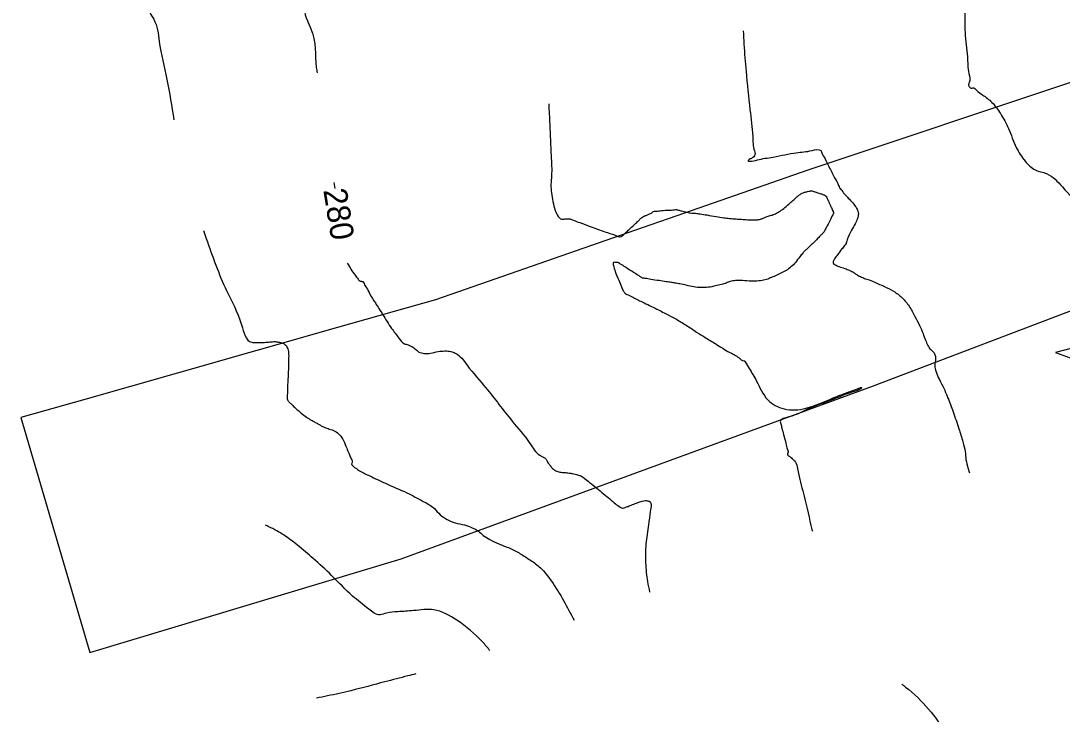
# Model space of a CAD drawing. Extents: x -478464 to -472469, y -1120963 to -1113785.
# Drawn here: x -476249.6 to -476071.3, y -1115360.9 to -1115242.1 of the extents above; entities that cross this region are included whole.
import ezdxf

# ---------------------------------------------------------------- set-up
doc = ezdxf.new("R2010")
doc.units = 0
for name, color, linetype in [('ObPÚ', 7, 'Continuous'), ('Vrstevnice_hlavni', 7, 'Continuous'), ('Vrstevnice_popis', 7, 'Continuous'), ('Vrstevnice_vedlejsi', 7, 'Continuous')]:
    doc.layers.add(name, color=color, linetype=linetype)

msp = doc.modelspace()

# ---------------------------------------------------------------- linework, layer by layer
at = {"layer": 'ObPÚ'}
for points in [[(-476068.7, -1115252.31), (-476114.88, -1115267.73), (-476138.618, -1115276.003), (-476141.91, -1115277.15), (-476168.45, -1115286.39), (-476178.6, -1115289.93), (-476195.38, -1115294.7), (-476223.04, -1115302.55), (-476238.65, -1115306.98), (-476249.64, -1115310.1), (-476237.84, -1115350.34), (-476184.5, -1115334.29), (-476103.79, -1115304.74), (-476065.34, -1115290.09)], [(-476062.5, -1115296.39), (-476072.47, -1115298.98), (-476067.44, -1115300.76)]]:
    msp.add_lwpolyline(points, dxfattribs=at)
at = {"layer": 'Vrstevnice_hlavni'}
msp.add_line((-476196.015, -1115269.846), (-476195.861, -1115270.85), dxfattribs=at)
for points in [[(-476040.384, -1115118.458), (-476041.47, -1115119.89), (-476042.412, -1115121.448), (-476043.751, -1115123.849), (-476045.488, -1115127.091), (-476046.696, -1115129.513), (-476047.375, -1115131.113), (-476047.526, -1115131.894), (-476048.073, -1115133.254), (-476049.018, -1115135.194), (-476050.36, -1115137.713), (-476052.374, -1115140.598), (-476055.061, -1115143.847), (-476058.422, -1115147.462), (-476060.881, -1115150.366), (-476062.441, -1115152.562), (-476063.1, -1115154.048), (-476064.028, -1115155.224), (-476065.225, -1115156.09), (-476066.691, -1115156.645), (-476068.203, -1115157.501), (-476069.761, -1115158.657), (-476071.364, -1115160.113), (-476073.585, -1115161.644), (-476076.424, -1115163.251), (-476079.881, -1115164.932), (-476082.243, -1115166.084), (-476083.511, -1115166.709), (-476083.684, -1115166.806), (-476083.884, -1115166.906), (-476084.109, -1115167.009), (-476084.361, -1115167.115), (-476085.47, -1115168.111), (-476087.436, -1115169.998), (-476090.259, -1115172.776), (-476094.056, -1115175.649), (-476098.828, -1115178.618), (-476104.575, -1115181.683), (-476109.757, -1115183.949), (-476114.374, -1115185.417), (-476118.425, -1115186.088), (-476122.042, -1115187.328), (-476125.226, -1115189.137), (-476127.977, -1115191.516), (-476131.019, -1115193.792), (-476134.353, -1115195.963), (-476137.979, -1115198.031), (-476141.984, -1115199.581), (-476146.368, -1115200.612), (-476151.132, -1115201.124), (-476157.864, -1115204.368), (-476166.565, -1115210.343), (-476177.234, -1115219.049), (-476184.652, -1115224.996), (-476188.817, -1115228.184), (-476189.731, -1115228.613), (-476190.168, -1115228.886), (-476190.128, -1115229.002), (-476189.61, -1115228.963), (-476189.269, -1115228.999), (-476189.104, -1115229.11), (-476189.116, -1115229.298), (-476189.143, -1115229.675), (-476189.187, -1115230.241), (-476189.246, -1115230.996), (-476189.162, -1115231.612), (-476188.933, -1115232.089), (-476188.56, -1115232.427), (-476188.448, -1115232.74), (-476188.595, -1115233.026), (-476189.004, -1115233.287), (-476189.464, -1115233.625), (-476189.976, -1115234.04), (-476190.541, -1115234.531), (-476191.953, -1115235.382), (-476194.211, -1115236.59), (-476197.317, -1115238.157), (-476199.41, -1115239.209), (-476200.49, -1115239.748), (-476200.557, -1115239.773), (-476200.072, -1115243.239), (-476199.036, -1115250.148), (-476198.895, -1115251.068)], [(-476193.757, -1115283.639), (-476192.399, -1115285.697), (-476191.876, -1115286.389), (-476191.509, -1115286.744), (-476191.298, -1115286.761), (-476191.153, -1115286.774), (-476191.075, -1115286.783), (-476191.063, -1115286.789), (-476190.853, -1115287.151), (-476190.446, -1115287.871), (-476189.842, -1115288.948), (-476188.923, -1115290.467), (-476187.688, -1115292.429), (-476186.137, -1115294.833), (-476184.891, -1115296.504), (-476183.948, -1115297.443), (-476183.309, -1115297.648), (-476182.68, -1115297.954), (-476182.06, -1115298.362), (-476181.45, -1115298.872), (-476180.595, -1115299.114), (-476179.497, -1115299.088), (-476178.155, -1115298.795), (-476176.997, -1115298.69), (-476176.025, -1115298.773), (-476175.238, -1115299.045), (-476173.224, -1115301.122), (-476169.984, -1115305.003), (-476165.518, -1115310.689), (-476162.449, -1115314.535), (-476160.779, -1115316.54), (-476160.507, -1115316.704), (-476160.264, -1115316.845), (-476160.048, -1115316.962), (-476159.86, -1115317.056), (-476159.707, -1115317.19), (-476159.59, -1115317.365), (-476159.508, -1115317.58), (-476159.311, -1115317.896), (-476158.998, -1115318.315), (-476158.57, -1115318.834), (-476158.007, -1115319.207), (-476157.308, -1115319.433), (-476156.473, -1115319.513), (-476155.76, -1115319.601), (-476155.169, -1115319.698), (-476154.699, -1115319.804), (-476154.303, -1115319.906), (-476153.978, -1115320.004), (-476153.727, -1115320.098), (-476153.145, -1115320.495), (-476152.232, -1115321.193), (-476150.988, -1115322.193), (-476149.831, -1115323.145), (-476148.761, -1115324.046), (-476147.778, -1115324.899), (-476147.017, -1115325.426), (-476146.478, -1115325.629), (-476146.16, -1115325.507), (-476145.635, -1115325.303), (-476144.904, -1115325.017), (-476143.967, -1115324.649), (-476143.233, -1115324.414), (-476142.702, -1115324.312), (-476142.375, -1115324.342), (-476142.123, -1115324.398), (-476141.945, -1115324.481), (-476141.842, -1115324.59), (-476141.767, -1115324.715), (-476141.722, -1115324.858), (-476141.705, -1115325.018), (-476141.842, -1115326.221), (-476142.131, -1115328.466), (-476142.574, -1115331.753), (-476142.636, -1115334.999), (-476142.32, -1115338.203), (-476141.962, -1115339.984)]]:
    msp.add_spline(points, degree=3, dxfattribs=at)
at = {"layer": 'Vrstevnice_vedlejsi'}
for points in [[(-476075.436, -1115157.873), (-476077.562, -1115158.907), (-476079.639, -1115159.964), (-476081.666, -1115161.045), (-476083.644, -1115162.149), (-476085.921, -1115163.289), (-476088.498, -1115164.465), (-476091.373, -1115165.676), (-476093.656, -1115166.843), (-476095.346, -1115167.967), (-476096.444, -1115169.047), (-476097.921, -1115170.165), (-476099.777, -1115171.319), (-476102.012, -1115172.511), (-476105.743, -1115173.677), (-476110.97, -1115174.816), (-476117.692, -1115175.928), (-476122.561, -1115177.005), (-476125.576, -1115178.045), (-476126.738, -1115179.05), (-476129.738, -1115180.989), (-476134.578, -1115183.864), (-476141.257, -1115187.673), (-476147.035, -1115190.356), (-476151.912, -1115191.911), (-476155.888, -1115192.338), (-476158.789, -1115192.754), (-476160.614, -1115193.159), (-476161.364, -1115193.552), (-476162.517, -1115193.939), (-476164.073, -1115194.319), (-476166.032, -1115194.693), (-476167.609, -1115195.158), (-476168.804, -1115195.715), (-476169.616, -1115196.364), (-476170.816, -1115197.116), (-476172.405, -1115197.973), (-476174.383, -1115198.934), (-476179.537, -1115202.555), (-476187.868, -1115208.836), (-476199.377, -1115217.776), (-476207.75, -1115223.932), (-476212.989, -1115227.302), (-476215.093, -1115227.888), (-476217.31, -1115229.046), (-476219.639, -1115230.776), (-476222.081, -1115233.079), (-476224.102, -1115235.091), (-476225.704, -1115236.812), (-476226.884, -1115238.243), (-476227.475, -1115239.561), (-476227.475, -1115240.767), (-476226.885, -1115241.861), (-476225.939, -1115245.662), (-476224.639, -1115252.17), (-476223.41, -1115259.087)], [(-476083.589, -1115227.899), (-476083.618, -1115228.156), (-476083.747, -1115228.632), (-476083.919, -1115228.675), (-476084.163, -1115228.958), (-476084.479, -1115229.481), (-476084.868, -1115230.243), (-476085.18, -1115230.932), (-476085.415, -1115231.547), (-476085.574, -1115232.089), (-476085.972, -1115233.269), (-476086.609, -1115235.087), (-476087.484, -1115237.544), (-476087.928, -1115240.567), (-476087.94, -1115244.158), (-476087.519, -1115248.316), (-476087.274, -1115251.164), (-476087.204, -1115252.702), (-476087.311, -1115252.93), (-476087.328, -1115253.147), (-476087.257, -1115253.355), (-476087.098, -1115253.552), (-476086.936, -1115253.666), (-476086.772, -1115253.697), (-476086.607, -1115253.643), (-476085.981, -1115254.028), (-476084.895, -1115254.851), (-476083.349, -1115256.112), (-476081.88, -1115258.027), (-476080.487, -1115260.597), (-476079.172, -1115263.821), (-476077.645, -1115266.182), (-476075.907, -1115267.682), (-476073.958, -1115268.319), (-476071.269, -1115270.587), (-476067.84, -1115274.487), (-476063.671, -1115280.019), (-476060.648, -1115284.041), (-476058.772, -1115286.555), (-476058.043, -1115287.561), (-476057.529, -1115288.232), (-476057.228, -1115288.568), (-476057.142, -1115288.571), (-476057.059, -1115289.537), (-476056.98, -1115291.466)], [(-476125.929, -1115243.884), (-476125.807, -1115246.158), (-476125.427, -1115250.782), (-476124.774, -1115257.383), (-476124.301, -1115261.931), (-476124.008, -1115264.426), (-476123.894, -1115264.868), (-476123.981, -1115265.246), (-476124.269, -1115265.56), (-476124.757, -1115265.811), (-476125.029, -1115265.996), (-476125.083, -1115266.115), (-476124.92, -1115266.169), (-476123.491, -1115265.956), (-476120.797, -1115265.476), (-476116.836, -1115264.728), (-476114.123, -1115264.363), (-476112.657, -1115264.382), (-476112.438, -1115264.783), (-476111.966, -1115265.692), (-476111.241, -1115267.111), (-476110.263, -1115269.038), (-476109.58, -1115270.343), (-476109.193, -1115271.027), (-476109.102, -1115271.089), (-476109.038, -1115271.136), (-476109.003, -1115271.169), (-476108.995, -1115271.186), (-476108.962, -1115271.248), (-476108.904, -1115271.357), (-476108.821, -1115271.512), (-476108.502, -1115271.894), (-476107.946, -1115272.505), (-476107.155, -1115273.343), (-476106.601, -1115274.081), (-476106.285, -1115274.719), (-476106.206, -1115275.258), (-476106.359, -1115275.986), (-476106.744, -1115276.905)], [(-476159.242, -1115256.374), (-476159.054, -1115259.908), (-476158.82, -1115265.295), (-476158.75, -1115268.706), (-476158.845, -1115270.139), (-476158.769, -1115271.604), (-476158.523, -1115273.101), (-476158.106, -1115274.629), (-476157.613, -1115275.635), (-476157.044, -1115276.119), (-476156.398, -1115276.081), (-476155.961, -1115276.055), (-476155.733, -1115276.04), (-476155.713, -1115276.036), (-476155.581, -1115276.081), (-476155.338, -1115276.173), (-476154.983, -1115276.314), (-476153.911, -1115276.714), (-476152.122, -1115277.373), (-476149.617, -1115278.29), (-476147.877, -1115278.87), (-476146.903, -1115279.111), (-476146.694, -1115279.015), (-476146.533, -1115278.92), (-476146.42, -1115278.827), (-476146.354, -1115278.736), (-476146.034, -1115278.42), (-476145.458, -1115277.878), (-476144.627, -1115277.111), (-476144.009, -1115276.53), (-476143.606, -1115276.135), (-476143.416, -1115275.928), (-476143.115, -1115275.721), (-476142.7, -1115275.515), (-476142.174, -1115275.31), (-476141.777, -1115275.132), (-476141.512, -1115274.98), (-476141.376, -1115274.855), (-476140.853, -1115274.744), (-476139.943, -1115274.647), (-476138.645, -1115274.565), (-476137.773, -1115274.512), (-476137.326, -1115274.488), (-476137.304, -1115274.493), (-476137.022, -1115274.564), (-476136.479, -1115274.699), (-476135.676, -1115274.9), (-476135.01, -1115275.037), (-476134.48, -1115275.109), (-476134.087, -1115275.117), (-476133.301, -1115275.213), (-476132.123, -1115275.399), (-476130.553, -1115275.673), (-476129.267, -1115275.873), (-476128.264, -1115275.998), (-476127.545, -1115276.049), (-476126.691, -1115276.105), (-476125.702, -1115276.169), (-476124.578, -1115276.238), (-476123.673, -1115276.222), (-476122.988, -1115276.122), (-476122.522, -1115275.938), (-476121.968, -1115275.735), (-476121.325, -1115275.516), (-476120.594, -1115275.279), (-476119.818, -1115274.872), (-476118.996, -1115274.295), (-476118.13, -1115273.548), (-476117.407, -1115272.922), (-476116.827, -1115272.417), (-476116.391, -1115272.033), (-476115.924, -1115271.733), (-476115.425, -1115271.516), (-476114.896, -1115271.383), (-476114.504, -1115271.301), (-476114.247, -1115271.269), (-476114.127, -1115271.287), (-476113.822, -1115271.374), (-476113.331, -1115271.529), (-476112.656, -1115271.752), (-476112.177, -1115271.921), (-476111.894, -1115272.035), (-476111.807, -1115272.094), (-476111.623, -1115272.416), (-476111.341, -1115273)], [(-476111.341, -1115273), (-476110.962, -1115273.848), (-476110.694, -1115274.441), (-476110.537, -1115274.78), (-476110.491, -1115274.865), (-476110.47, -1115274.959), (-476110.475, -1115275.062), (-476110.506, -1115275.174), (-476110.69, -1115275.573), (-476111.03, -1115276.26), (-476111.524, -1115277.233), (-476111.877, -1115277.912), (-476112.088, -1115278.296), (-476112.158, -1115278.386), (-476112.514, -1115278.752), (-476113.156, -1115279.397), (-476114.085, -1115280.319), (-476114.761, -1115280.979), (-476115.186, -1115281.379), (-476115.36, -1115281.517), (-476115.713, -1115281.919), (-476116.247, -1115282.585), (-476116.962, -1115283.514), (-476117.741, -1115284.291), (-476118.584, -1115284.915), (-476119.493, -1115285.387), (-476120.392, -1115285.812), (-476121.284, -1115286.191), (-476122.167, -1115286.523), (-476123.251, -1115286.707), (-476124.536, -1115286.741), (-476126.022, -1115286.628), (-476127.231, -1115286.643), (-476128.162, -1115286.786), (-476128.816, -1115287.059), (-476129.654, -1115287.316), (-476130.678, -1115287.555), (-476131.887, -1115287.779), (-476133.124, -1115287.833), (-476134.388, -1115287.719), (-476135.68, -1115287.435), (-476136.751, -1115287.215), (-476137.602, -1115287.058), (-476138.232, -1115286.963), (-476139.134, -1115286.827), (-476140.308, -1115286.649), (-476141.754, -1115286.429), (-476142.752, -1115286.26), (-476143.303, -1115286.142), (-476143.406, -1115286.075), (-476143.876, -1115285.775), (-476144.711, -1115285.24), (-476145.912, -1115284.47), (-476146.719, -1115283.95), (-476147.131, -1115283.678), (-476147.149, -1115283.654), (-476147.194, -1115283.626), (-476147.267, -1115283.594), (-476147.366, -1115283.557), (-476147.542, -1115283.533), (-476147.795, -1115283.522), (-476148.124, -1115283.524), (-476148.141, -1115284.035), (-476147.848, -1115285.056), (-476147.243, -1115286.586), (-476146.785, -1115287.691), (-476146.474, -1115288.372), (-476146.31, -1115288.628), (-476146.156, -1115288.817), (-476146.012, -1115288.938), (-476145.878, -1115288.992), (-476144.948, -1115289.442), (-476143.224, -1115290.289), (-476140.705, -1115291.532), (-476138.75, -1115292.524), (-476137.361, -1115293.265), (-476136.537, -1115293.756), (-476135.685, -1115294.285), (-476134.806, -1115294.853), (-476133.899, -1115295.46), (-476132.503, -1115296.342), (-476130.618, -1115297.498), (-476128.243, -1115298.929), (-476126.641, -1115299.885), (-476125.811, -1115300.366), (-476125.755, -1115300.372), (-476125.7, -1115300.405), (-476125.646, -1115300.464), (-476125.594, -1115300.551), (-476124.922, -1115301.679), (-476123.631, -1115303.848), (-476121.721, -1115307.059), (-476118.902, -1115308.612), (-476115.176, -1115308.508), (-476110.541, -1115306.747), (-476107.432, -1115305.567), (-476105.848, -1115304.97)], [(-476218.376, -1115278.038), (-476217.875, -1115279.456), (-476214.425, -1115288.313), (-476211.835, -1115294.229), (-476210.106, -1115297.205), (-476209.237, -1115297.241), (-476208.349, -1115297.236), (-476207.441, -1115297.189), (-476206.512, -1115297.099), (-476205.696, -1115297.136), (-476204.991, -1115297.297), (-476204.399, -1115297.584), (-476203.999, -1115298.149), (-476203.792, -1115298.991), (-476203.779, -1115300.111), (-476203.805, -1115301.478), (-476203.871, -1115303.093), (-476203.978, -1115304.956), (-476204.004, -1115306.275), (-476203.949, -1115307.051), (-476203.815, -1115307.284), (-476203.415, -1115307.714), (-476202.75, -1115308.342), (-476201.819, -1115309.168), (-476200.943, -1115309.859), (-476200.122, -1115310.415), (-476199.355, -1115310.837), (-476198.758, -1115311.169), (-476198.331, -1115311.411), (-476198.073, -1115311.564), (-476197.577, -1115311.782), (-476196.841, -1115312.065), (-476195.867, -1115312.414), (-476195.041, -1115313.077), (-476194.362, -1115314.054), (-476193.831, -1115315.346), (-476193.423, -1115316.323), (-476193.136, -1115316.986), (-476192.972, -1115317.333), (-476192.894, -1115317.625), (-476192.903, -1115317.861)], [(-476106.744, -1115276.905), (-476107.361, -1115278.014), (-476107.805, -1115278.877), (-476108.078, -1115279.493), (-476108.177, -1115279.862), (-476108.25, -1115280.122), (-476108.297, -1115280.271), (-476108.317, -1115280.311), (-476108.573, -1115280.647), (-476109.065, -1115281.28), (-476109.793, -1115282.209), (-476110.279, -1115282.913), (-476110.525, -1115283.392), (-476110.528, -1115283.645), (-476110.197, -1115283.923), (-476109.532, -1115284.226), (-476108.532, -1115284.553), (-476107.69, -1115284.894), (-476107.005, -1115285.251), (-476106.478, -1115285.622), (-476105.861, -1115285.956), (-476105.153, -1115286.251), (-476104.354, -1115286.507), (-476103.257, -1115286.96), (-476101.863, -1115287.61), (-476100.172, -1115288.455), (-476098.717, -1115289.598), (-476097.498, -1115291.039), (-476096.516, -1115292.777), (-476095.725, -1115294.323), (-476095.126, -1115295.678), (-476094.718, -1115296.841), (-476094.281, -1115297.767), (-476093.815, -1115298.456), (-476093.319, -1115298.907), (-476093.04, -1115299.473), (-476092.976, -1115300.153), (-476093.128, -1115300.947), (-476092.975, -1115301.971), (-476092.517, -1115303.223), (-476091.755, -1115304.704), (-476090.913, -1115306.661), (-476089.99, -1115309.094), (-476088.988, -1115312.004), (-476088.293, -1115314.278), (-476087.906, -1115315.919), (-476087.826, -1115316.925), (-476087.506, -1115318.414), (-476087.193, -1115319.54)], [(-476105.848, -1115304.97), (-476105.79, -1115304.953), (-476105.742, -1115304.95), (-476105.706, -1115304.96), (-476105.681, -1115304.983), (-476105.665, -1115305.007), (-476105.66, -1115305.032), (-476105.665, -1115305.057), (-476105.684, -1115305.087), (-476105.717, -1115305.122), (-476105.765, -1115305.16), (-476107.334, -1115305.771), (-476110.427, -1115306.953), (-476115.042, -1115308.707), (-476118.091, -1115309.993), (-476119.575, -1115310.812), (-476119.492, -1115311.162), (-476119.302, -1115311.898), (-476119.003, -1115313.019), (-476118.597, -1115314.525), (-476118.349, -1115315.58), (-476118.261, -1115316.183), (-476118.333, -1115316.335), (-476118.325, -1115316.469), (-476118.238, -1115316.585), (-476118.073, -1115316.683), (-476117.836, -1115316.872), (-476117.529, -1115317.152), (-476117.151, -1115317.523), (-476116.463, -1115319.666), (-476115.466, -1115323.582), (-476114.16, -1115329.271), (-476114.085, -1115329.578)], [(-476192.903, -1115317.861), (-476192.999, -1115318.042), (-476192.816, -1115318.327), (-476192.354, -1115318.716), (-476191.613, -1115319.21), (-476189.891, -1115320.089), (-476187.188, -1115321.354), (-476183.505, -1115323.005), (-476180.713, -1115324.453), (-476178.814, -1115325.697), (-476177.806, -1115326.737), (-476176.612, -1115327.549), (-476175.23, -1115328.132), (-476173.662, -1115328.486), (-476172.346, -1115328.961), (-476171.282, -1115329.555), (-476170.47, -1115330.27), (-476169.305, -1115330.996), (-476167.786, -1115331.732), (-476165.913, -1115332.48), (-476164.102, -1115333.412), (-476162.353, -1115334.527), (-476160.666, -1115335.826), (-476158.775, -1115338.132), (-476156.681, -1115341.444), (-476154.893, -1115344.811)], [(-476169.317, -1115349.984), (-476170.582, -1115348.511), (-476174.959, -1115344.81), (-476178.893, -1115343.028), (-476182.384, -1115343.164), (-476185.085, -1115343.353), (-476186.997, -1115343.594), (-476188.119, -1115343.887), (-476190.063, -1115342.911), (-476192.828, -1115340.664), (-476196.414, -1115337.147), (-476199.562, -1115334.239), (-476202.271, -1115331.942), (-476204.542, -1115330.254), (-476207.149, -1115328.799), (-476207.747, -1115328.526)], [(-476181.992, -1115354.005), (-476183.366, -1115354.351), (-476187.292, -1115355.365), (-476193.102, -1115356.883), (-476197.096, -1115357.776), (-476199.01, -1115358.158)], [(-476098.759, -1115355.772), (-476098.104, -1115356.265), (-476094.169, -1115360.055), (-476091.29, -1115364.289), (-476089.469, -1115368.968), (-476087.31, -1115373.303), (-476084.815, -1115377.295), (-476081.983, -1115380.943), (-476080.049, -1115383.349), (-476079.012, -1115384.513), (-476078.873, -1115384.435), (-476077.604, -1115386.121), (-476075.204, -1115389.571), (-476071.674, -1115394.785), (-476069.552, -1115401.62), (-476068.838, -1115410.075), (-476069.531, -1115420.149), (-476069.805, -1115427.952), (-476069.661, -1115433.483), (-476069.097, -1115436.741), (-476068.496, -1115441.851), (-476067.856, -1115448.811), (-476067.178, -1115457.621), (-476066.359, -1115464.997), (-476065.399, -1115470.938), (-476064.298, -1115475.444), (-476063.04, -1115480.506), (-476061.623, -1115486.124), (-476060.048, -1115492.299), (-476057.359, -1115498.807), (-476053.555, -1115505.649), (-476048.638, -1115512.824), (-476045.2, -1115517.862), (-476043.242, -1115520.763), (-476042.765, -1115521.525), (-476042.192, -1115522.181), (-476041.525, -1115522.73), (-476040.763, -1115523.173), (-476040.038, -1115523.283), (-476039.35, -1115523.061), (-476038.7, -1115522.505), (-476038.329, -1115521.94), (-476038.238, -1115521.364), (-476038.426, -1115520.777), (-476038.547, -1115520.357), (-476038.601, -1115520.103), (-476038.589, -1115520.015), (-476037.572, -1115516.059), (-476035.551, -1115508.234), (-476032.525, -1115496.54), (-476029.317, -1115488.206), (-476025.926, -1115483.231), (-476022.353, -1115481.616), (-476019.314, -1115477.601), (-476016.81, -1115471.188), (-476014.84, -1115462.377), (-476007.652, -1115456.21), (-475995.247, -1115452.687), (-475977.623, -1115451.809), (-475965.182, -1115450.685), (-475957.923, -1115449.314)]]:
    msp.add_spline(points, degree=3, dxfattribs=at)

# ---------------------------------------------------------------- texts
at = {"layer": 'Vrstevnice_popis'}
msp.add_text(' 280 ', height=4, rotation=279.08544, dxfattribs=at).set_placement((-476198.078, -1115269.663))

doc.saveas('drawing.dxf')
